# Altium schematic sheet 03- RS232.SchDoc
size A4; DocumentNumber: 15; SheetNumber: 15; SheetTotal: 15
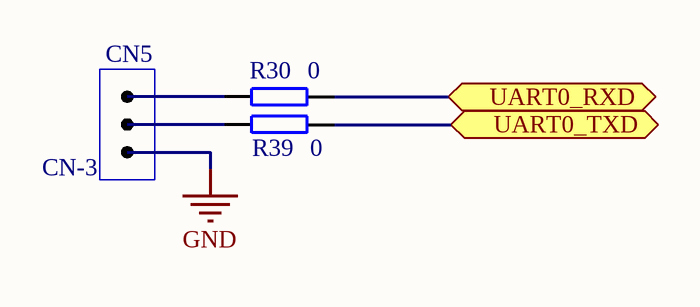
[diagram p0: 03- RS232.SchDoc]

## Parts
CN5  CN-3  [SIP-3(2.54)]
R30  0  [R0402]
R39  0  [R0402]

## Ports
UART0_RXD (bidir), UART0_TXD (bidir)

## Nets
GND: CN5.3
UART0_RXD: R30.1 ; port UART0_RXD
UART0_TXD: R39.1 ; port UART0_TXD
NetCN5_1: CN5.1 R30.2
NetCN5_2: CN5.2 R39.2

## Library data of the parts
R30 R39 = 电阻Ω: Resistor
